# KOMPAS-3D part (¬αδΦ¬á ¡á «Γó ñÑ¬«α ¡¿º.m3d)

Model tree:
1. Эскиз:1
2. Операция выдавливания:1
     Расстояние 1 = 2
3. Эскиз:2
4. Вырезать элемент выдавливания:1
     Расстояние 1 = 10; Угол 1 = 35
5. Эскиз:3
6. Вырезать элемент выдавливания:2
     Расстояние 1 = 10
7. Эскиз:4
8. Операция выдавливания:2
     Расстояние 1 = 10; Расстояние 2 = 2
9. Операция выдавливания:3
     Расстояние 1 = 0.6
